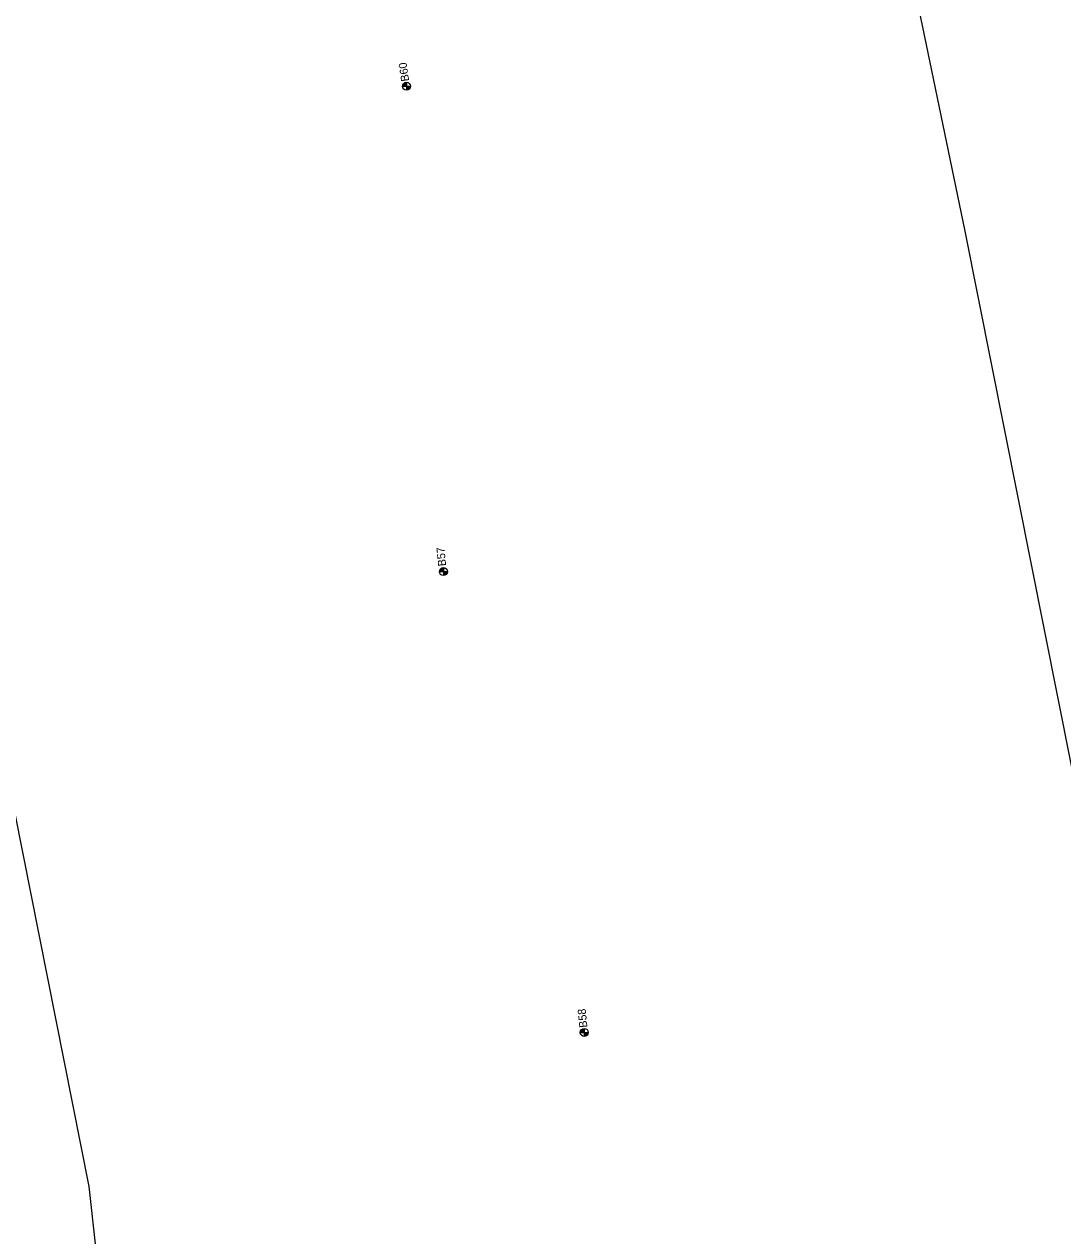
# Model space of a CAD drawing. Extents: x 311409 to 379449, y 121539 to 224848.
# Drawn here: x 359420 to 360717, y 160877 to 162391 of the extents above; entities that cross this region are included whole.
import ezdxf

# ---------------------------------------------------------------- set-up
doc = ezdxf.new("R2010")
doc.units = 0
for name, color, linetype in [('E_SOIL_BORE1 [KAPUR_CADDS_LEVELS]', 7, 'Continuous'), ('E_SOIL_BORE2 [KAPUR_CADDS_LEVELS]', 7, 'Continuous'), ('P_MARK', 7, 'Continuous'), ('P_TC', 7, 'Continuous')]:
    doc.layers.add(name, color=color, linetype=linetype)

msp = doc.modelspace()

# ---------------------------------------------------------------- linework, layer by layer
at = {"layer": 'P_MARK'}
for p, q in [((359892.4, 162313.3), (359902.4, 162313.3)), ((359897.4, 162318.3), (359897.4, 162308.3)), ((359938.5, 161706.9), (359948.5, 161706.9)), ((359943.5, 161711.9), (359943.5, 161701.9)), ((360114.5, 161131), (360124.5, 161131)), ((360119.5, 161136), (360119.5, 161126))]:
    msp.add_line(p, q, dxfattribs=at)
for centre in [(359897.4, 162313.3), (359943.5, 161706.9), (360119.5, 161131)]:
    msp.add_circle(centre, 5, dxfattribs=at)
for centre, radius, start, end in [((359897.4, 162313.3), 4.5, 89.9869, 179.9869), ((359897.4, 162313.3), 4, 89.9869, 179.9869), ((359897.4, 162313.3), 3.5, 89.9869, 179.9869), ((359897.4, 162313.3), 3, 89.9869, 179.9869), ((359897.4, 162313.3), 2.5, 89.9869, 179.9869), ((359897.4, 162313.3), 2, 89.9869, 179.9869), ((359897.4, 162313.3), 1.5, 89.9869, 179.9869), ((359897.4, 162313.3), 1, 89.9869, 179.9869), ((359897.4, 162313.3), 0.5, 89.9869, 179.9869), ((359897.4, 162313.3), 4.5, 269.9869, 359.9869), ((359897.4, 162313.3), 4, 269.9869, 359.9869), ((359897.4, 162313.3), 3.5, 269.9869, 359.9869), ((359897.4, 162313.3), 3, 269.9869, 359.9869), ((359897.4, 162313.3), 2.5, 269.9869, 359.9869), ((359897.4, 162313.3), 2, 269.9869, 359.9869), ((359897.4, 162313.3), 1.5, 269.9869, 359.9869), ((359897.4, 162313.3), 1, 269.9869, 359.9869), ((359897.4, 162313.3), 0.5, 269.9869, 359.9869), ((359943.5, 161706.9), 4.5, 89.9869, 179.9869), ((359943.5, 161706.9), 4, 89.9869, 179.9869), ((359943.5, 161706.9), 3.5, 89.9869, 179.9869), ((359943.5, 161706.9), 3, 89.9869, 179.9869), ((359943.5, 161706.9), 2.5, 89.9869, 179.9869), ((359943.5, 161706.9), 2, 89.9869, 179.9869), ((359943.5, 161706.9), 1.5, 89.9869, 179.9869), ((359943.5, 161706.9), 1, 89.9869, 179.9869), ((359943.5, 161706.9), 0.5, 89.9869, 179.9869), ((359943.5, 161706.9), 4.5, 269.9869, 359.9869), ((359943.5, 161706.9), 4, 269.9869, 359.9869), ((359943.5, 161706.9), 3.5, 269.9869, 359.9869), ((359943.5, 161706.9), 3, 269.9869, 359.9869), ((359943.5, 161706.9), 2.5, 269.9869, 359.9869), ((359943.5, 161706.9), 2, 269.9869, 359.9869), ((359943.5, 161706.9), 1.5, 269.9869, 359.9869), ((359943.5, 161706.9), 1, 269.9869, 359.9869), ((359943.5, 161706.9), 0.5, 269.9869, 359.9869), ((360119.5, 161131), 4.5, 89.9869, 179.9869), ((360119.5, 161131), 4, 89.9869, 179.9869), ((360119.5, 161131), 3.5, 89.9869, 179.9869), ((360119.5, 161131), 3, 89.9869, 179.9869), ((360119.5, 161131), 2.5, 89.9869, 179.9869), ((360119.5, 161131), 2, 89.9869, 179.9869), ((360119.5, 161131), 1.5, 89.9869, 179.9869), ((360119.5, 161131), 1, 89.9869, 179.9869), ((360119.5, 161131), 0.5, 89.9869, 179.9869), ((360119.5, 161131), 4.5, 269.9869, 359.9869), ((360119.5, 161131), 4, 269.9869, 359.9869), ((360119.5, 161131), 3.5, 269.9869, 359.9869), ((360119.5, 161131), 3, 269.9869, 359.9869), ((360119.5, 161131), 2.5, 269.9869, 359.9869), ((360119.5, 161131), 2, 269.9869, 359.9869), ((360119.5, 161131), 1.5, 269.9869, 359.9869), ((360119.5, 161131), 1, 269.9869, 359.9869), ((360119.5, 161131), 0.5, 269.9869, 359.9869)]:
    msp.add_arc(centre, radius, start, end, dxfattribs=at)
at = {"layer": 'P_TC'}
for points in [[(361967.2, 148742.4), (361289.2, 151524), (361150.4, 152029.3), (361085.6, 152465.4), (360932.2, 153930.3), (360925.6, 158686.2), (360924.7, 159340.4), (360899.9, 160010), (360888, 160413.6), (360826.8, 160968.6), (360595.4, 162132.3), (360355.1, 163291.2), (360178.1, 164047.2)], [(358874.4, 163917.9), (359033, 163240.2), (359272.2, 162086.7), (359500.6, 160938.4), (359558.7, 160410.8), (359570.3, 160019.2), (359595.2, 159348.4), (359596, 158698.2), (359602.4, 153949.6), (359759.4, 152437.1), (359827.1, 151981.3), (359969.9, 151461.4), (360646.7, 148684.4)]]:
    msp.add_lwpolyline(points, dxfattribs=at)

# ---------------------------------------------------------------- texts
at = {"layer": 'E_SOIL_BORE1 [KAPUR_CADDS_LEVELS]'}
for s, rotation, p in [('B60', 98.5151, (359900.8, 162320.1)), ('B57', 95.5802, (359947, 161714.1))]:
    msp.add_text(s, height=10, rotation=rotation, dxfattribs=at).set_placement(p)
at = {"layer": 'E_SOIL_BORE2 [KAPUR_CADDS_LEVELS]'}
msp.add_text('B58', height=10, rotation=95.5802, dxfattribs=at).set_placement((360123.4, 161137.4))

doc.saveas('drawing.dxf')
